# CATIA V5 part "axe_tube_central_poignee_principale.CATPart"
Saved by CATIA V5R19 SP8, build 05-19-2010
Part number: axe_tube_central_rail
Bounding box of the stored display mesh (mm): x 0 to 60, y -5 to 5, z -5 to 5
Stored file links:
  U:\Thinkmotion\Assemblage final\axe_tube_central_poignee_principale.CATPart
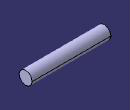
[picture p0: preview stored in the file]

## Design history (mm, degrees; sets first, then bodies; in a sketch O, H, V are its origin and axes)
Body1 (main body)
  Sketch1 on yz-plane, origin (0, 0, 0), H (0, 1, 0), V (0, 0, 1)
    circle A1 centre (0, 0) radius 5
    radius A1 = 5
  Pad1: profile Sketch1, direction (1, 0, 0), length 60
